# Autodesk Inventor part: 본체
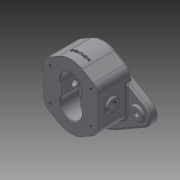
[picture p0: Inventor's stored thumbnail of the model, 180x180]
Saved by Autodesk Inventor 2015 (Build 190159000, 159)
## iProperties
Created: 2025-11
Part Number: 본체
Material: 일반
Document SubType Name: Modeling
Designer: user
Density: 1 g/cm^3
Appearance: 기본값
Author: user
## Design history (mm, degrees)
sketch "스케치1"
  geometry: L1 (74, 17.321)-(26, 45.033); L2 (-74, 17.321)-(-26, 45.033); L3 (74, -17.321)-(26, -45.033); L4 (-26, -45.033)-(-74, -17.321); A1 r 52 centre (0, 0) between (26, 45.033) and (-26, 45.033); A2 r 20 centre (-64, 0) between (-74, -17.321) and (-74, 17.321); A3 r 20 centre (64, 0) between (74, 17.321) and (74, -17.321); 1 further point
  constraints: 8 end point, 8 point on circle, 8 tangent, 3 centre point, 2 horizontal alignment, 1 coincident
  dimensions: "d0" = 104 diameter of A1; "d1" = 40 diameter of A2; "d2" = 40 diameter of A3; "d3" = 64 distance of A2.centre point (0, 0); "d4" = 64 distance of A3.centre point (0, 0)
extrude "돌출1" new body sketch "스케치1" distance "d5" = 12; taper "d6" = 0 deg
sketch "스케치2"
  geometry: L1 (-96.076, 16)-(99.755, 16); L2 (-19, 64.909)-(-45, 49.898); L3 (-45, 49.898)-(-45, -17.898); L4 (-45, -17.898)-(-19, -32.909); L5 (0, 0)-(0, 32); L6 (19, 64.909)-(45, 49.898); L7 (45, 49.898)-(45, -17.898); L8 (45, -17.898)-(19, -32.909); A1 r 52 centre (0, 0) between (-26, -45.033) and (26, -45.033) reference; A2 r 52 centre (0, 0) between (26, 45.033) and (-26, 45.033) reference; A3 r 38 centre (0, 0) between (-19, -32.909) and (19, -32.909); A4 r 38 centre (0, 32) between (-19, 64.909) and (19, 64.909)
  constraints: 16 end point, 4 point on circle, 2 centre point, 2 tangent, 2 vertical, 1 coincident, 1 horizontal, 1 parallel, 1 vertical alignment, 2 other
  dimensions: "d7" = 76 diameter of A3; "d8" = 16 distance from line of L1 A1.centre; "d9" = 76 diameter of A4; "d10" = 16 distance from line of L1 L5.end; "d11" = 60 deg angle of L4 L2; "d12" = 60 deg angle of L8 L6; "d13" = 45 distance from line of A1.centre L3; "d14" = 90 distance between parallel lines of L3 L7
extrude "돌출2" join sketch "스케치2" distance "d15" = 48; taper "d17" = 0 deg; dims "d16" = 8, "d18" = 0
sketch "스케치3"
  geometry: L1 (-16, 0)-(16, 0); L2 (16, 0)-(16, 32); L3 (16, 32)-(-16, 32); L4 (-16, 32)-(-16, 0); C1 r 18 at (0, 32); C2 r 18 at (0, 0); A1 r 38 centre (0, 32) between (19, 64.909) and (-19, 64.909) reference; A2 r 38 centre (0, 0) between (-19, -32.909) and (19, -32.909) reference
  constraints: 8 end point, 2 centre point, 2 coincident, 2 midpoint, 2 parallel, 1 horizontal, 1 perpendicular
  dimensions: "d19" = 36 diameter of C1; "d20" = 36 diameter of C2; "d21" = 16 distance from line of A2.centre L4; "d22" = 32 distance between parallel lines of L2 L4
extrude "돌출3" cut sketch "스케치3" distance "d23" = 31; taper "d24" = 0 deg
sketch "스케치4"
  geometry: L1 (0, 0)-(51.962, 0) reference; L2 (51.962, -48)-(-15.834, -48) reference; L3 (25.817, -48)-(10.31, -48) reference; L4 (18.064, -48)-(18.064, 0); C1 r 10 at (18.064, -25); 1 further point
  constraints: 2 end point, 2 point on line, 1 centre point, 1 midpoint, 1 perpendicular
  dimensions: "d25" = 20 diameter of C1; "d26" = 23 distance from line of L2 C1.centre
extrude "돌출4" join sketch "스케치4" distance "d27" = 3; taper "d28" = 0 deg
sketch "스케치5"
  geometry: C1 r 10 at (0, 0) reference; 1 further point
hole "구멍1" sketch "스케치5" at (0, 0) diameter "d29" = 10.5; stored, may be unused: countersink angle "d35" = 90 deg, drill point angle "d37" = 118 deg; dims "d30" = 11, "d31" = 0.62479, "d32" = 10.589, "d33" = 4, "d34" = 2, "d36" = 17.5
sketch "스케치6"
  geometry: L1 (16, 8.246)-(16, 23.754) reference; L2 (-16, 23.754)-(-16, 8.246) reference; L3 (19, 64.909)-(45, 49.898) reference; L4 (45, 49.898)-(45, 22) reference; L5 (45, 22)-(48, 22) reference; L6 (48, 22)-(48, 10) reference; L7 (48, 10)-(45, 10) reference; L8 (45, 10)-(45, -17.898) reference; L9 (45, -17.898)-(19, -32.909) reference; L10 (-19, -32.909)-(-45, -17.898) reference; L11 (-45, -17.898)-(-45, 10) reference; L12 (-45, 10)-(-48, 10) reference; L13 (-48, 10)-(-48, 22) reference; L14 (-48, 22)-(-45, 22) reference; L15 (-45, 22)-(-45, 49.898) reference; L16 (-45, 49.898)-(-19, 64.909) reference; L17 (-48, 16)-(48, 16); C1 r 11.5 at (0, 32); C2 r 11.5 at (0, 0); A1 r 18 centre (0, 32) between (16, 23.754) and (-16, 23.754) reference; A2 r 18 centre (0, 32) between (16, 23.754) and (-16, 23.754) reference; A3 r 18 centre (0, 0) between (-16, 8.246) and (16, 8.246) reference; A4 r 38 centre (0, 32) between (19, 64.909) and (-19, 64.909) reference; A5 r 38 centre (0, 0) between (-19, -32.909) and (19, -32.909) reference
  constraints: 2 centre point, 2 end point, 2 midpoint, 1 coincident, 1 vertical alignment
  dimensions: "d38" = 23 diameter of C1; "d39" = 23 diameter of C2; "d40" = 16 distance from line of C2.centre L17
extrude "돌출5" cut sketch "스케치6" distance "d41" = 15; taper "d42" = 0 deg
sketch "스케치7"
  geometry: C1 r 25 at (0, 0); A1 r 18 centre (0, 0) between (16, -8.246) and (-16, -8.246) reference
  constraints: 1 centre point, 1 coincident
  dimensions: "d43" = 50 diameter of C1
extrude "돌출6" join sketch "스케치7" distance "d44" = 4; taper "d45" = 0 deg
sketch "스케치8"
  geometry: C1 r 25 at (0, 0) reference; C2 r 15 at (0, 0)
  constraints: 1 centre point, 1 coincident
  dimensions: "d46" = 30 diameter of C2
extrude "돌출7" cut sketch "스케치8" distance "d47" = 7.3; taper "d48" = 0 deg
sketch "스케치9"
  geometry: C1 r 15 at (0, 0) reference; C2 r 10.5 at (0, 0)
  constraints: 1 centre point, 1 coincident
  dimensions: "d49" = 21 diameter of C2
extrude "돌출8" cut sketch "스케치9" stored distance "d50" = 7.3; taper "d51" = 0 deg
sketch "스케치10"
  geometry: C1 r 10 at (-64, 0); C2 r 10 at (64, 0); A1 r 20 centre (-64, 0) between (-74, 17.321) and (-74, -17.321) reference; A2 r 20 centre (64, 0) between (74, -17.321) and (74, 17.321) reference
  constraints: 2 centre point, 2 coincident
  dimensions: "d52" = 20 diameter of C1; "d53" = 20 diameter of C2
extrude "돌출9" join sketch "스케치10" distance "d54" = 3; taper "d55" = 0 deg
sketch "스케치11"
  geometry: L1 (83, 64.909)-(109, 49.898) reference; L2 (109, 49.898)-(109, -17.898) reference; L3 (109, -17.898)-(83, -32.909) reference; L4 (45, -32.909)-(19, -17.898) reference; L5 (19, -17.898)-(19, 49.898) reference; L6 (19, 49.898)-(45, 64.909) reference; C1 r 10 at (0, 0) reference; C2 r 10 at (0, 0) reference; C3 r 10 at (128, 0) reference; C4 r 11.5 at (64, 32) reference; C5 r 11.5 at (64, 0) reference; A1 r 38 centre (64, 32) between (83, 64.909) and (45, 64.909) reference; A2 r 38 centre (64, 0) between (45, -32.909) and (83, -32.909) reference; 1 further point
hole "구멍2" sketch "스케치11" at (0, 0), (128, 0) diameter "d56" = 9; stored, may be unused: countersink angle "d60" = 90 deg, drill point angle "d62" = 118 deg; dims "d57" = 11, "d58" = 4, "d59" = 2, "d61" = 17.5
sketch "스케치12"
  geometry: L1 (-48, 6)-(-48, 26) reference; L2 (-45, 6)-(-45, 26) reference; L3 (48, 6)-(48, 26) reference; L4 (-48, 10.362)-(-48, 21.638) reference; L5 (-48, 16)-(48, 16); L6 (0, 32)-(0, 0); L7 (-34, 43)-(34, 43); L8 (34, 43)-(34, -11); L9 (34, -11)-(-34, -11); L10 (-34, -11)-(-34, 43); A1 r 38 centre (0, 32) between (19, 64.909) and (-19, 64.909) reference; A2 r 38 centre (0, 0) between (-19, -32.909) and (19, -32.909) reference
  constraints: 12 end point, 2 midpoint, 2 parallel, 1 horizontal, 1 perpendicular, 1 vertical
  dimensions: "d63" = 68 distance of L8.end L9.end; "d64" = 54 distance of L7.end L8.end; "d65" = 34 distance between parallel lines of L6 L10; "d66" = 27 distance between parallel lines of L5 L7
hole "구멍3" sketch "스케치12" at (-34, 43), (-34, -11), (34, -11), (34, 43) diameter "d67" = 4.917; stored, may be unused: countersink angle "d71" = 90 deg, drill point angle "d73" = 118 deg; dims "d68" = 12, "d69" = 4, "d70" = 2, "d72" = 14
fillet "모깎기1" dims "d74" = 15
fillet "모깎기2" dims "d75" = 3
fillet "모깎기3" dims "d76" = 3
chamfer "모따기1" distance "d77" = 1; stored, may be unused: second distance "d78" = 2, angle "d79" = 45 deg
fillet "모깎기4" dims "d80" = 0.3
chamfer "모따기2" distance "d81" = 0.7; stored, may be unused: second distance "d82" = 2, angle "d83" = 30 deg
node "작업 평면1"
sketch "스케치13"
  geometry: L1 (37.5, -48)-(19, -48) reference; 2 further points
  constraints: 1 vertical alignment, 1 other
  dimensions: "d84" = 16 distance from line of L1 point (0, -32)
feature "엠보싱1" sketch "스케치13" dims "d0" = 104, "d1" = 40, "d2" = 40, "d3" = 64, "d4" = 64, "d85" = 0.5, "d86" = 0
node "솔리드1"
mirror "대칭1"
mirror "대칭2"
node "투영된 루프1"
node "절단 모서리 투영1"
node "절단 모서리 투영2"
